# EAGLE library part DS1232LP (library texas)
Low Power MicroMonitor Chip Source: DALLAS SEMICONDUCTOR .. 1232lp.pdf
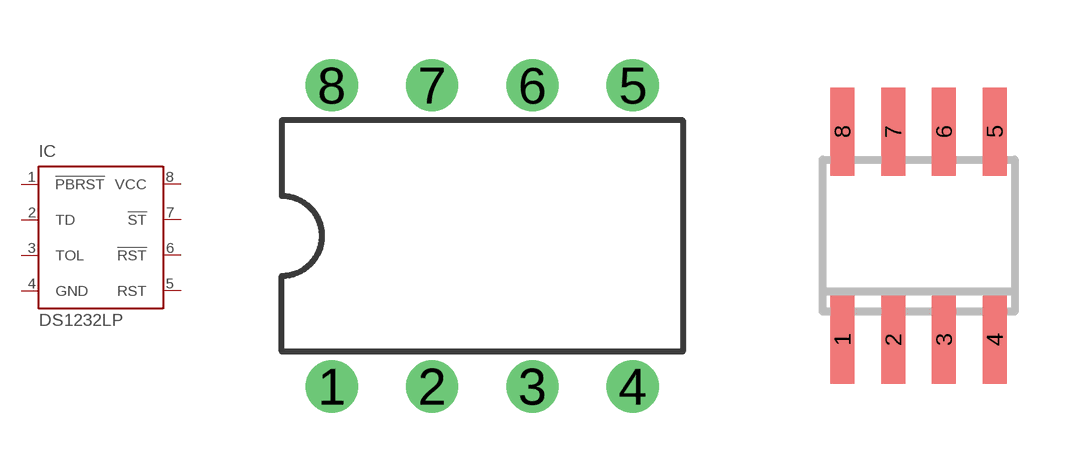
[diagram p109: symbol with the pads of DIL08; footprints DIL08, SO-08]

Designator prefix IC

## DS1232LP (MPN: DS1232LP+; OC_FARNELL: 1187997; OC_NEWARK: 68K3327)  [DIL08]
1  !PBRST  in
2  TD  in
3  TOL  in
4  GND  pwr
5  RST  out
6  !RST  out
7  !ST  in
8  VCC  pwr

## DS1232LPS-2 (MF: DALLAS SEMICONDUCTOR; MPN: DS1232LPS-2; OC_FARNELL: 9724877; OC_NEWARK: 06F4304)  [SO-08]
Pads as for DIL08

## DS1232LPS (MPN: DS1232LPS+; OC_FARNELL: unknown; OC_NEWARK: 99K1954)  [SO-16DW]
2  !PBRST  in
4  TD  in
6  TOL  in
8  GND  pwr
9  RST  out
11  !RST  out
13  !ST  in
15  VCC  pwr

## Footprint DIL08 (pad centres in mm)
Dual In Line Package
drill 0.813 pad 1.27 round: 1 -3.81,-3.81; 2 -1.27,-3.81; 3 1.27,-3.81; 4 3.81,-3.81; 5 3.81,3.81; 6 1.27,3.81; 7 -1.27,3.81; 8 -3.81,3.81

## Footprint SO-08 (pad centres in mm)
D (R-PDSO-G8) Plastic Small Outline Package Source: http://focus.ti.com/lit/ds/symlink/sn65als176.pdf
smd 0.6 x 2.2: 1 -1.905,-2.6; 2 -0.635,-2.6; 3 0.635,-2.6; 4 1.905,-2.6; 5 1.905,2.6; 6 0.635,2.6; 7 -0.635,2.6; 8 -1.905,2.6

## Footprint SO-16DW (pad centres in mm)
DW (RPDSO-G16) Source: http://focus.ti.com/lit/ds/symlink/iso1176.pdf
smd 0.6 x 2.2: 1 -4.445,-4.6; 2 -3.175,-4.6; 3 -1.905,-4.6; 4 -0.635,-4.6; 5 0.635,-4.6; 6 1.905,-4.6; 7 3.175,-4.6; 8 4.445,-4.6; 9 4.445,4.6; 10 3.175,4.6; 11 1.905,4.6; 12 0.635,4.6; 13 -0.635,4.6; 14 -1.905,4.6; 15 -3.175,4.6; 16 -4.445,4.6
